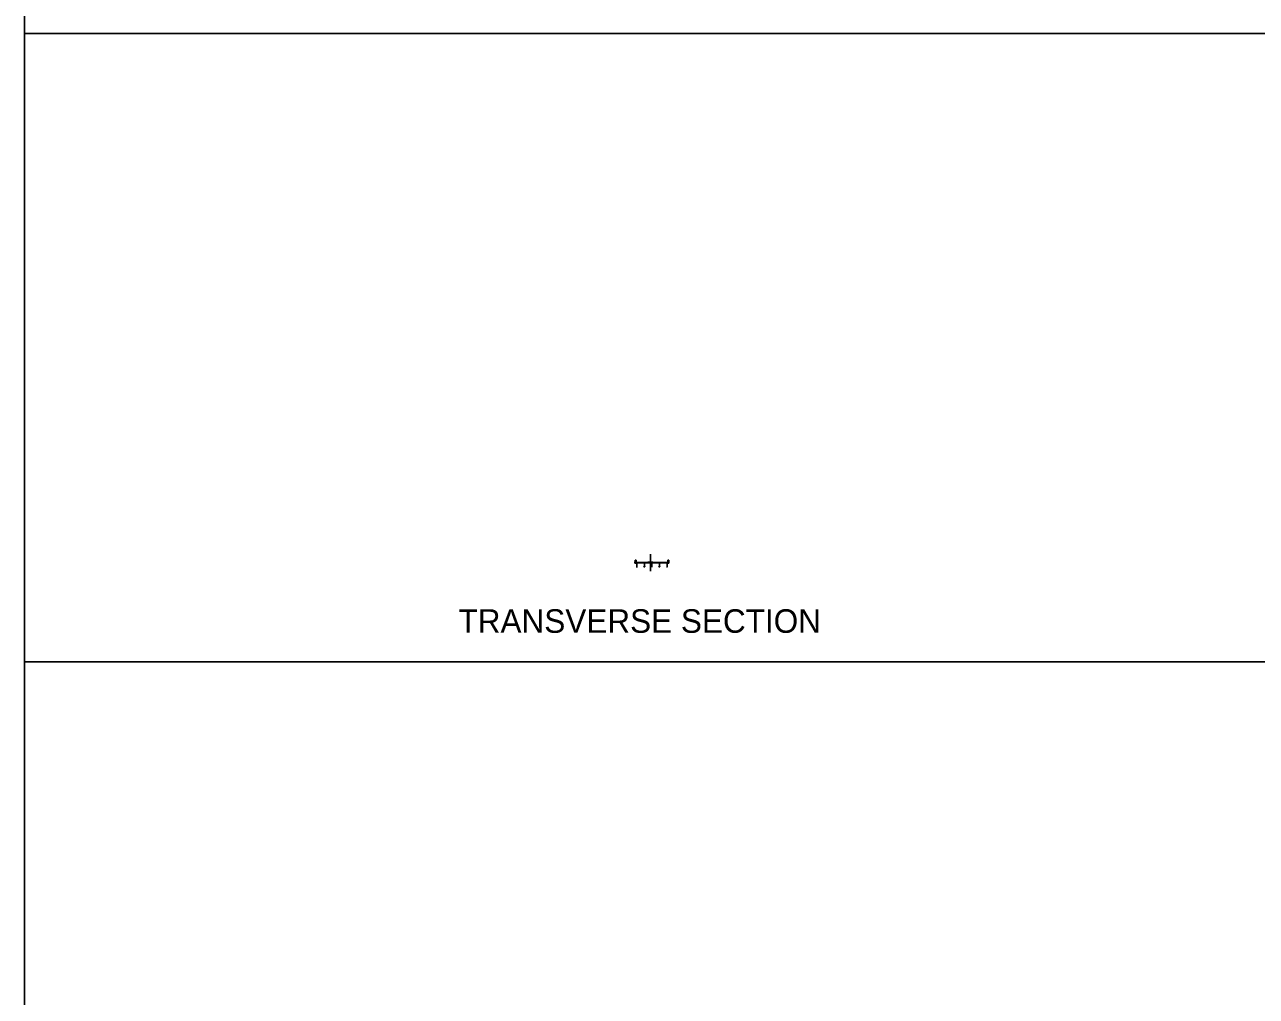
# Model space of a CAD drawing. Extents: x -6598 to 6602, y -3155 to 3145.
# Drawn here: x -1598 to -30, y 420 to 1657 of the extents above; entities that cross this region are included whole.
import ezdxf

# ---------------------------------------------------------------- set-up
doc = ezdxf.new("R2010")
doc.units = 0
for name, color, linetype in [('BridgeExistingStructure', 7, 'Continuous'), ('Removals', 7, 'Continuous'), ('ShtPlotShapeBatchPrint', 7, 'Continuous')]:
    doc.layers.add(name, color=color, linetype=linetype)

msp = doc.modelspace()

# ---------------------------------------------------------------- linework, layer by layer
at = {"layer": 'BridgeExistingStructure'}
for p, q in [((-820.5, 973), (-821.5, 973)), ((-821.5, 973), (-821.5, 972)), ((-820.1, 974.9), (-821, 974.9)), ((-821, 974.9), (-821, 973)), ((-820.5, 973), (-820, 972.9)), ((-820.1, 974.9), (-820.1, 972.9)), ((-820, 972.9), (-819.9, 972.1)), ((-801.9, 972.2), (-801.9, 972.2)), ((-779.8, 972.9), (-779.8, 972)), ((-779.3, 972.9), (-779.8, 972.9)), ((-779.6, 974.9), (-778.4, 974.9)), ((-779.6, 974.9), (-779.6, 972.9)), ((-779.3, 972.9), (-778.2, 972.9)), ((-778.4, 974.9), (-778.4, 972.9)), ((-778.2, 972.9), (-778.2, 971.9)), ((-821.5, 971.9), (-819.9, 972)), ((-821.5, 971.9), (-821.5, 972)), ((-821.5, 971.9), (-821.5, 971.3)), ((-821.5, 971.9), (-821.5, 971.9)), ((-821.5, 971.3), (-821.3, 971.3)), ((-821.3, 971.3), (-821.2, 971.3)), ((-821.3, 971.3), (-821.3, 971.3)), ((-821.2, 971.3), (-819.8, 971.2)), ((-819.8, 971.3), (-819.8, 971.1)), ((-819.8, 971.3), (-818.4, 971.3)), ((-818.4, 971.2), (-819.8, 971.2)), ((-818.4, 971.1), (-819.8, 971.1)), ((-818.4, 966.7), (-819.8, 966.7)), ((-819.8, 966.5), (-819.8, 966.7)), ((-818.4, 966.6), (-819.8, 966.6)), ((-819.8, 966.5), (-818.4, 966.5)), ((-819.1, 966.7), (-819.1, 971.1)), ((-819.1, 966.7), (-819.1, 971.1)), ((-818.4, 971.3), (-810.2, 971.4)), ((-818.4, 971.3), (-818.4, 971.3)), ((-818.4, 971.3), (-818.4, 971.1)), ((-818.4, 966.5), (-818.4, 966.7)), ((-810.2, 971.4), (-810.2, 971.4)), ((-810.2, 971.4), (-810.2, 971.2)), ((-810.2, 971.4), (-808.8, 971.4)), ((-808.8, 971.3), (-810.2, 971.3)), ((-808.8, 971.2), (-810.2, 971.2)), ((-808.8, 966.9), (-810.2, 966.9)), ((-810.2, 966.7), (-810.2, 966.9)), ((-808.8, 966.8), (-810.2, 966.8)), ((-810.2, 966.7), (-808.8, 966.7)), ((-809.5, 966.9), (-809.5, 971.2)), ((-809.5, 966.9), (-809.5, 971.2)), ((-808.8, 971.5), (-801.9, 971.6)), ((-808.8, 971.4), (-808.8, 971.5)), ((-808.8, 971.4), (-808.8, 971.2)), ((-808.8, 966.7), (-808.8, 966.9)), ((-800.5, 971.6), (-801.9, 971.6)), ((-800.5, 971.5), (-800.5, 971.6)), ((-800.5, 971.5), (-800.5, 971.3)), ((-800.5, 971.5), (-799.2, 971.5)), ((-799.2, 971.4), (-800.5, 971.4)), ((-799.2, 971.3), (-800.5, 971.3)), ((-799.2, 967), (-800.5, 967)), ((-800.5, 966.8), (-800.5, 967)), ((-799.2, 966.9), (-800.5, 966.9)), ((-800.5, 966.8), (-799.2, 966.8)), ((-799.9, 967), (-799.9, 971.3)), ((-799.8, 967), (-799.8, 971.3)), ((-799.2, 971.5), (-799.2, 971.5)), ((-790.9, 971.4), (-799.2, 971.5)), ((-799.2, 971.5), (-799.2, 971.3)), ((-799.2, 966.8), (-799.2, 967)), ((-790.9, 971.4), (-790.9, 971.4)), ((-790.9, 971.4), (-790.9, 971.1)), ((-790.9, 971.4), (-789.6, 971.4)), ((-789.6, 971.3), (-790.9, 971.3)), ((-789.6, 971.1), (-790.9, 971.1)), ((-789.6, 966.8), (-790.9, 966.8)), ((-790.9, 966.6), (-790.9, 966.8)), ((-789.6, 966.7), (-790.9, 966.7)), ((-790.9, 966.6), (-789.6, 966.6)), ((-790.2, 966.8), (-790.2, 971.1)), ((-790.2, 966.8), (-790.2, 971.1)), ((-789.6, 971.4), (-789.6, 971.4)), ((-781.3, 971.3), (-789.6, 971.4)), ((-789.6, 971.4), (-789.6, 971.1)), ((-789.6, 966.6), (-789.6, 966.8)), ((-781.3, 971.2), (-781.3, 971.3)), ((-781.3, 971.2), (-781.3, 971)), ((-781.3, 971.2), (-779.9, 971.2)), ((-779.9, 971.1), (-781.3, 971.1)), ((-779.9, 971), (-781.3, 971)), ((-779.9, 966.7), (-781.3, 966.7)), ((-781.3, 966.5), (-781.3, 966.7)), ((-779.9, 966.6), (-781.3, 966.6)), ((-781.3, 966.5), (-779.9, 966.5)), ((-780.6, 966.7), (-780.6, 971)), ((-780.6, 966.7), (-780.6, 971)), ((-778.3, 971.9), (-779.9, 971.9)), ((-778.5, 971.2), (-779.9, 971.1)), ((-779.9, 971.2), (-779.9, 971)), ((-779.9, 966.5), (-779.9, 966.7)), ((-778.4, 971.3), (-778.5, 971.2)), ((-778.4, 971.3), (-778.4, 971.2)), ((-778.2, 971.2), (-778.4, 971.2)), ((-778.3, 971.9), (-778.2, 971.9)), ((-778.3, 971.9), (-778.2, 971.8)), ((-778.2, 971.8), (-778.2, 971.2))]:
    msp.add_line(p, q, dxfattribs=at)
msp.add_circle((-779, 972.4), 0.0833, dxfattribs=at)
at = {"layer": 'Removals'}
for p, q in [((-819.9, 972.1), (-804.9, 972.3)), ((-779.8, 972), (-798.9, 972.3)), ((-819.9, 971.9), (-804.9, 972.2)), ((-819.9, 972.1), (-819.9, 972)), ((-819.9, 972), (-819.9, 971.9)), ((-779.9, 971.9), (-798.9, 972.2)), ((-779.8, 972), (-779.9, 971.9)), ((-779.9, 971.9), (-779.9, 971.9))]:
    msp.add_line(p, q, dxfattribs=at)
for centre in [(-801.9, 672.3), (-801.9, 672.2)]:
    msp.add_arc(centre, 300, 89.427, 90.573, dxfattribs=at)
at = {"layer": 'ShtPlotShapeBatchPrint'}
msp.add_line((-801.9, 961.2), (-801.9, 982.8), dxfattribs=at)
for points in [[(-1598.4, 3045.4), (1601.6, 3045.4), (1601.6, 1645.4), (-1598.4, 1645.4)], [(-1598.4, 1645.4), (1.6, 1645.4), (1.6, 845.4), (-1598.4, 845.4)], [(-1598.4, 845.4), (1.6, 845.4), (1.6, 45.4), (-1598.4, 45.4)]]:
    msp.add_lwpolyline(points, close=True, dxfattribs=at)

# ---------------------------------------------------------------- texts
msp.add_text('TRANSVERSE SECTION', height=30, dxfattribs=at).set_placement((-1046.1, 882.5))

doc.saveas('drawing.dxf')
